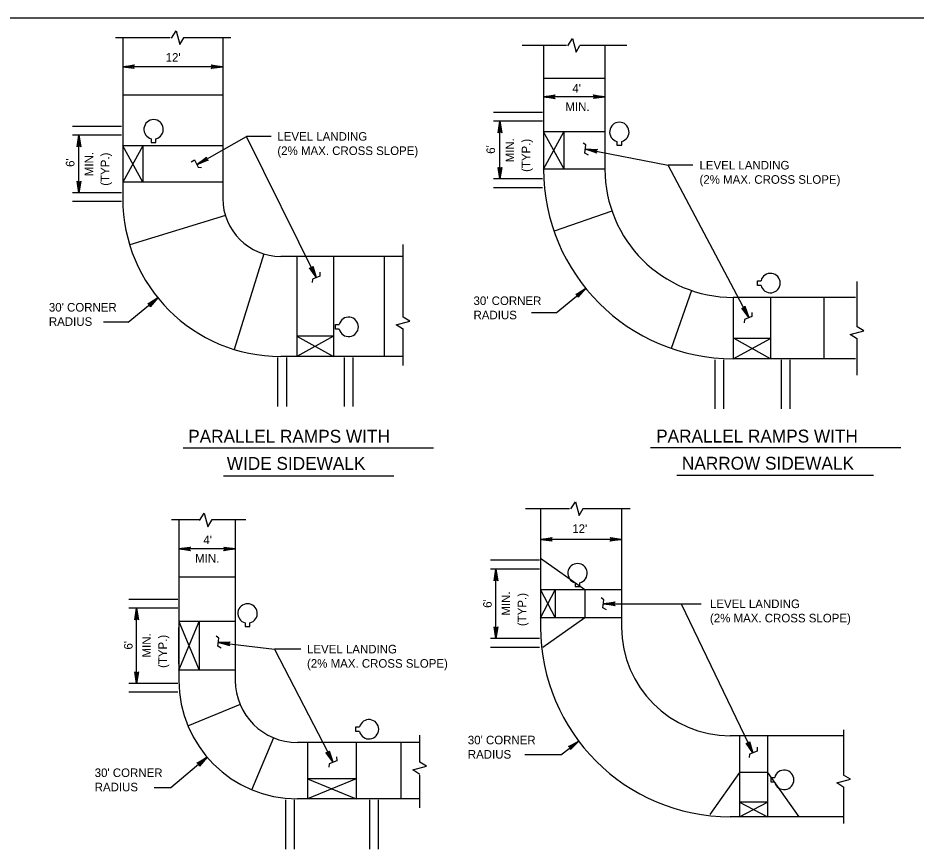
# Model space of a CAD drawing. Extents: x -344 to 940, y 22 to 1233.
# Drawn here: x 84.3 to 398.4, y 310.4 to 601.2 of the extents above; entities that cross this region are included whole.
import ezdxf

# ---------------------------------------------------------------- set-up
doc = ezdxf.new("R2010")
doc.units = 0
doc.layers.add('1', color=7, linetype='Continuous')
doc.layers.add('2', color=7, linetype='Continuous')

msp = doc.modelspace()

# ---------------------------------------------------------------- linework, layer by layer
at = {"layer": '1'}
msp.add_line((75.86, 601.17), (861.86, 601.17), dxfattribs=at)
at = {"layer": '2'}
for p, q in [((137.56, 594.17), (118.38, 594.17)), ((120.93, 594.17), (120.93, 538.02)), ((158.71, 594.17), (142.18, 594.17)), ((155.93, 594.17), (155.93, 538.02)), ((276.13, 591.48), (260.66, 591.48)), ((268.14, 591.48), (268.14, 548.28)), ((297.29, 591.48), (280.76, 591.48)), ((289.58, 591.48), (289.58, 548.28)), ((155.93, 584.11), (120.93, 584.11)), ((289.58, 579.99), (268.14, 579.99)), ((155.93, 574.19), (120.93, 574.19)), ((289.58, 573.58), (268.14, 573.58)), ((267.77, 568.08), (250.6, 568.08)), ((120.56, 563.24), (103.39, 563.24)), ((267.77, 565.01), (250.6, 565.01)), ((252.86, 544.85), (252.86, 565.01)), ((120.56, 560.17), (103.39, 560.17)), ((105.64, 540.01), (105.64, 560.17)), ((146.96, 549.94), (164.24, 559.7)), ((172.85, 559.7), (164.24, 559.7)), ((188.6, 510.44), (164.24, 559.7)), ((289.58, 561.32), (268.14, 561.32)), ((275.22, 548.54), (268.14, 561.32)), ((268.14, 548.28), (275.22, 561.32)), ((275.22, 561.32), (275.22, 548.54)), ((155.93, 556.48), (120.93, 556.48)), ((128.01, 543.7), (120.93, 556.48)), ((128.01, 556.48), (120.93, 543.7)), ((128.01, 556.48), (128.01, 543.7)), ((130.91, 558.91), (130.91, 557.61)), ((130.91, 557.61), (132.56, 557.61)), ((132.56, 557.61), (132.56, 558.91)), ((293.79, 558), (293.79, 556.7)), ((293.79, 556.7), (295.45, 556.7)), ((295.45, 556.7), (295.45, 558)), ((282.85, 555.28), (311.73, 549.64)), ((289.58, 548.28), (268.14, 548.28)), ((320.33, 549.64), (311.73, 549.64)), ((339.89, 496.41), (311.73, 549.64)), ((155.93, 543.7), (120.93, 543.7)), ((267.77, 544.85), (250.6, 544.85)), ((267.77, 541.78), (250.6, 541.78)), ((120.56, 540.01), (103.39, 540.01)), ((120.56, 536.94), (103.39, 536.94)), ((156.83, 532.06), (123.37, 521.78)), ((292.05, 533.62), (271.78, 526.61)), ((219, 496.52), (219, 521.92)), ((170.24, 518.65), (159.96, 485.19)), ((219, 517.75), (176.2, 517.75)), ((181.88, 517.75), (181.88, 482.75)), ((194.66, 517.75), (194.66, 482.75)), ((212.37, 517.75), (212.37, 482.75)), ((342.89, 507.6), (342.89, 509.26)), ((342.89, 509.26), (344.19, 509.26)), ((377.8, 493.14), (377.8, 508.95)), ((272.5, 498.03), (282.95, 506.5)), ((319.81, 505.86), (312.8, 485.59)), ((344.19, 507.6), (342.89, 507.6)), ((122.82, 494.73), (133.27, 503.21)), ((377.26, 503.39), (334.47, 503.39)), ((334.47, 503.39), (334.47, 481.95)), ((347.51, 503.39), (347.51, 481.95)), ((366.18, 503.39), (366.18, 481.95)), ((272.5, 498.03), (263.9, 498.03)), ((122.82, 494.73), (114.22, 494.73)), ((195.35, 492.29), (195.35, 493.94)), ((195.35, 493.94), (196.65, 493.94)), ((196.65, 492.29), (195.35, 492.29)), ((219, 479.61), (219, 492.28)), ((194.66, 489.83), (181.88, 489.83)), ((181.88, 489.83), (194.66, 482.75)), ((194.66, 489.83), (181.88, 482.75)), ((334.47, 481.95), (347.51, 489.03)), ((347.51, 489.03), (334.73, 489.03)), ((347.51, 481.95), (334.73, 489.03)), ((377.8, 476.22), (377.8, 488.89)), ((175.12, 482.38), (175.12, 465.21)), ((219, 482.75), (176.2, 482.75)), ((178.19, 482.38), (178.19, 465.21)), ((198.35, 482.38), (198.35, 465.21)), ((201.42, 482.38), (201.42, 465.21)), ((327.97, 481.58), (327.97, 464.41)), ((331.04, 481.58), (331.04, 464.41)), ((377.26, 481.95), (334.47, 481.95)), ((351.2, 481.58), (351.2, 464.41)), ((354.27, 481.58), (354.27, 464.41)), ((142.08, 450.77), (229.65, 450.77)), ((393.13, 450.77), (305.56, 450.77)), ((156.19, 440.95), (215.73, 440.95)), ((383.51, 441.16), (314.76, 441.16)), ((277.23, 429.45), (261.76, 429.45)), ((267.1, 429.45), (267.1, 388.07)), ((298.38, 429.45), (281.86, 429.45)), ((295.43, 429.45), (295.43, 388.07)), ((147.98, 425.58), (138.03, 425.58)), ((140.57, 425.58), (140.57, 369.43)), ((163.99, 425.58), (152, 425.58)), ((160.29, 425.58), (160.29, 369.43)), ((295.43, 418.78), (267.1, 418.78)), ((160.29, 415.43), (140.57, 415.43)), ((282.55, 401.12), (267.1, 412.06)), ((266.74, 411.45), (249.57, 411.45)), ((266.74, 408.38), (249.57, 408.38)), ((251.45, 384.07), (251.45, 408.38)), ((160.29, 405.6), (140.57, 405.6)), ((279.18, 403.61), (279.18, 402.31)), ((279.18, 402.31), (280.83, 402.31)), ((280.83, 402.31), (280.83, 403.61)), ((295.43, 401.12), (267.1, 401.12)), ((267.1, 401.12), (272.17, 391.33)), ((267.1, 391.33), (272.17, 401.12)), ((272.17, 401.12), (272.17, 391.33)), ((282.55, 401.12), (282.55, 391.33)), ((140.21, 397.72), (123.04, 397.72)), ((289.1, 396.22), (323.27, 396.22)), ((316.27, 396.22), (341.26, 344.13)), ((140.21, 394.65), (123.04, 394.65)), ((125.78, 368.35), (125.78, 394.65)), ((160.29, 390.02), (140.57, 390.02)), ((140.57, 390.02), (147.65, 372.99)), ((140.57, 372.99), (147.65, 390.02)), ((147.65, 390.02), (147.65, 372.99)), ((163.78, 389.54), (163.78, 388.24)), ((165.43, 388.24), (165.43, 389.54)), ((295.43, 391.33), (267.1, 391.33)), ((282.55, 391.33), (267.9, 380.96)), ((140.57, 375.11), (140.57, 387.89)), ((163.78, 388.24), (165.43, 388.24)), ((266.74, 384.07), (249.57, 384.07)), ((154.43, 382.71), (174.05, 380.35)), ((183.17, 380.35), (174.05, 380.35)), ((174.05, 380.35), (194.39, 340.92)), ((266.74, 381), (249.57, 381)), ((160.29, 372.99), (140.57, 372.99)), ((140.21, 368.35), (123.04, 368.35)), ((140.21, 365.28), (123.04, 365.28)), ((161.98, 361.05), (143.61, 353.37)), ((202.47, 351.52), (202.47, 353.17)), ((202.47, 353.17), (203.77, 353.17)), ((373.1, 336.29), (373.1, 352.1)), ((173.64, 349.38), (165.97, 331.01)), ((203.77, 351.52), (202.47, 351.52)), ((224.83, 340.84), (224.83, 350.3)), ((373.1, 350.08), (333.43, 350.08)), ((336.68, 350.08), (336.68, 321.75)), ((346.47, 350.08), (346.47, 321.75)), ((224.83, 347.7), (182.03, 347.7)), ((185.58, 347.7), (185.58, 327.98)), ((202.62, 347.7), (202.62, 327.98)), ((218.2, 347.7), (218.2, 327.98)), ((274.12, 343.44), (280.43, 348.19)), ((150.42, 342.61), (137.74, 331.85)), ((274.12, 343.44), (261.52, 343.44)), ((224.83, 324.83), (224.83, 336.3)), ((336.68, 337.19), (326.31, 322.55)), ((346.47, 337.19), (336.68, 337.19)), ((346.47, 337.19), (357.41, 321.75)), ((202.62, 335.05), (185.58, 335.05)), ((185.58, 335.05), (202.62, 327.98)), ((202.62, 335.05), (185.58, 327.98)), ((347.67, 333.82), (347.67, 335.48)), ((347.67, 335.48), (348.97, 335.48)), ((348.97, 333.82), (347.67, 333.82)), ((137.74, 331.85), (131.91, 331.85)), ((373.1, 319.37), (373.1, 332.05)), ((177.88, 327.61), (177.88, 310.44)), ((180.95, 327.61), (180.95, 310.44)), ((224.83, 327.98), (182.03, 327.98)), ((207.25, 327.61), (207.25, 310.44)), ((210.32, 327.61), (210.32, 310.44)), ((346.47, 326.82), (336.68, 326.82)), ((336.68, 326.82), (346.47, 321.75)), ((336.68, 321.75), (346.47, 326.82)), ((373.1, 321.75), (333.43, 321.75))]:
    msp.add_line(p, q, dxfattribs=at)
for points in [[(137.98, 594.14), (139.67, 596.62), (140.93, 591.88), (142.29, 594.25)], [(276.56, 591.46), (278.24, 593.94), (279.51, 589.2), (280.86, 591.57)], [(124.79, 583.62), (124.65, 583.9), (120.93, 584.11), (124.79, 583.62), (124.99, 583.45), (120.93, 584.11), (124.64, 584.29), (124.78, 584.57), (120.93, 584.11), (124.99, 584.75), (124.78, 584.57)], [(152.07, 584.59), (152.22, 584.31), (155.93, 584.11), (152.07, 584.59), (151.87, 584.76), (155.93, 584.11), (152.22, 583.92), (152.08, 583.65), (155.93, 584.11), (151.87, 583.46), (152.08, 583.65)], [(272, 573.1), (271.86, 573.38), (268.14, 573.58), (272, 573.1), (272.2, 572.93), (268.14, 573.58), (271.85, 573.77), (271.99, 574.04), (268.14, 573.58), (272.2, 574.23), (271.99, 574.04)], [(285.72, 574.07), (285.87, 573.79), (289.58, 573.58), (285.72, 574.07), (285.53, 574.24), (289.58, 573.58), (285.87, 573.4), (285.74, 573.12), (289.58, 573.58), (285.53, 572.94), (285.74, 573.12)], [(252.37, 561.15), (252.65, 561.29), (252.86, 565.01), (252.37, 561.15), (252.2, 560.95), (252.86, 565.01), (253.04, 561.3), (253.32, 561.16), (252.86, 565.01), (253.5, 560.95), (253.32, 561.16)], [(105.16, 556.31), (105.44, 556.46), (105.64, 560.17), (105.16, 556.31), (104.99, 556.11), (105.64, 560.17), (105.83, 556.46), (106.1, 556.32), (105.64, 560.17), (106.29, 556.11), (106.1, 556.32)], [(283.82, 553.2), (282.6, 553.89), (282.96, 556.73), (282.02, 557.37)], [(286.55, 554.07), (286.46, 554.37), (282.85, 555.28), (286.55, 554.07), (286.71, 553.86), (282.85, 555.28), (286.53, 554.75), (286.72, 555), (282.85, 555.28), (286.96, 555.14), (286.72, 555)], [(144.82, 550.89), (146.05, 551.51), (147.29, 548.92), (148.43, 548.89)], [(150.56, 551.42), (150.3, 551.59), (146.96, 549.94), (150.56, 551.42), (150.82, 551.37), (146.96, 549.94), (150.1, 551.93), (150.09, 552.24), (146.96, 549.94), (150.18, 552.5), (150.09, 552.24)], [(253.34, 548.71), (253.06, 548.57), (252.86, 544.85), (253.34, 548.71), (253.51, 548.91), (252.86, 544.85), (252.67, 548.56), (252.4, 548.7), (252.86, 544.85), (252.21, 548.91), (252.4, 548.7)], [(106.13, 543.87), (105.85, 543.73), (105.64, 540.01), (106.13, 543.87), (106.3, 544.07), (105.64, 540.01), (105.46, 543.73), (105.18, 543.86), (105.64, 540.01), (105, 544.07), (105.18, 543.86)], [(187.32, 514.12), (187.13, 513.86), (188.6, 510.44), (187.32, 514.12), (187.39, 514.37), (188.6, 510.44), (186.79, 513.69), (186.48, 513.69), (188.6, 510.44), (186.22, 513.79), (186.48, 513.69)], [(189.87, 512.22), (189.92, 510.87), (187.27, 509.77), (187.18, 508.63)], [(279.65, 504.44), (279.94, 504.32), (282.95, 506.5), (279.65, 504.44), (279.39, 504.45), (282.95, 506.5), (280.18, 504.02), (280.25, 503.72), (282.95, 506.5), (280.21, 503.44), (280.25, 503.72)], [(129.97, 501.15), (130.26, 501.03), (133.27, 503.21), (129.97, 501.15), (129.71, 501.16), (133.27, 503.21), (130.5, 500.73), (130.57, 500.43), (133.27, 503.21), (130.53, 500.15), (130.57, 500.43)], [(338.51, 500.05), (338.33, 499.79), (339.89, 496.41), (338.51, 500.05), (338.57, 500.3), (339.89, 496.41), (337.99, 499.61), (337.68, 499.6), (339.89, 496.41), (337.42, 499.7), (337.68, 499.6)], [(219.08, 492.15), (216.6, 493.84), (221.34, 495.1), (218.97, 496.46)], [(340.94, 498.11), (340.98, 496.76), (338.34, 495.66), (338.25, 494.53)], [(377.88, 488.77), (375.4, 490.45), (380.14, 491.72), (377.77, 493.08)], [(277.65, 429.42), (279.34, 431.9), (280.6, 427.17), (281.96, 429.53)], [(147.77, 425.42), (149.46, 427.9), (150.72, 423.16), (152.08, 425.53)], [(270.96, 418.3), (270.82, 418.58), (267.1, 418.78), (270.96, 418.3), (271.16, 418.13), (267.1, 418.78), (270.82, 418.97), (270.95, 419.24), (267.1, 418.78), (271.16, 419.43), (270.95, 419.24)], [(291.57, 419.27), (291.72, 418.99), (295.43, 418.78), (291.57, 419.27), (291.37, 419.44), (295.43, 418.78), (291.72, 418.6), (291.58, 418.32), (295.43, 418.78), (291.37, 418.14), (291.58, 418.32)], [(144.43, 414.94), (144.29, 415.22), (140.57, 415.43), (144.43, 414.94), (144.63, 414.77), (140.57, 415.43), (144.29, 415.61), (144.42, 415.89), (140.57, 415.43), (144.63, 416.07), (144.42, 415.89)], [(156.43, 415.91), (156.58, 415.63), (160.29, 415.43), (156.43, 415.91), (156.24, 416.08), (160.29, 415.43), (156.58, 415.24), (156.45, 414.97), (160.29, 415.43), (156.24, 414.78), (156.45, 414.97)], [(250.96, 404.52), (251.24, 404.66), (251.45, 408.38), (250.96, 404.52), (250.79, 404.32), (251.45, 408.38), (251.63, 404.67), (251.91, 404.53), (251.45, 408.38), (252.09, 404.32), (251.91, 404.53)], [(290.09, 394.13), (288.87, 394.82), (289.23, 397.66), (288.29, 398.3)], [(292.96, 395.74), (292.82, 396.02), (289.1, 396.22), (292.96, 395.74), (293.16, 395.57), (289.1, 396.22), (292.82, 396.41), (292.95, 396.68), (289.1, 396.22), (293.16, 396.87), (292.95, 396.68)], [(125.29, 390.79), (125.57, 390.94), (125.78, 394.65), (125.29, 390.79), (125.12, 390.59), (125.78, 394.65), (125.96, 390.94), (126.24, 390.8), (125.78, 394.65), (126.42, 390.59), (126.24, 390.8)], [(251.93, 387.93), (251.65, 387.79), (251.45, 384.07), (251.93, 387.93), (252.1, 388.13), (251.45, 384.07), (251.26, 387.78), (250.99, 387.92), (251.45, 384.07), (250.8, 388.13), (250.99, 387.92)], [(155.4, 380.7), (154.18, 381.4), (154.54, 384.24), (153.6, 384.88)], [(158.21, 381.77), (158.1, 382.06), (154.43, 382.71), (158.21, 381.77), (158.38, 381.58), (154.43, 382.71), (158.14, 382.45), (158.31, 382.71), (154.43, 382.71), (158.54, 382.87), (158.31, 382.71)], [(126.26, 372.21), (125.98, 372.07), (125.78, 368.35), (126.26, 372.21), (126.43, 372.41), (125.78, 368.35), (125.59, 372.07), (125.32, 372.2), (125.78, 368.35), (125.13, 372.41), (125.32, 372.2)], [(277.06, 346.26), (277.34, 346.12), (280.43, 348.19), (277.06, 346.26), (276.8, 346.27), (280.43, 348.19), (277.58, 345.81), (277.64, 345.51), (280.43, 348.19), (277.58, 345.24), (277.64, 345.51)], [(340.03, 347.82), (339.84, 347.56), (341.26, 344.13), (340.03, 347.82), (340.1, 348.07), (341.26, 344.13), (339.49, 347.39), (339.18, 347.4), (341.26, 344.13), (338.93, 347.51), (339.18, 347.4)], [(342.77, 346.05), (342.81, 344.7), (340.17, 343.6), (340.08, 342.47)], [(147.16, 340.48), (147.45, 340.36), (150.42, 342.61), (147.16, 340.48), (146.9, 340.48), (150.42, 342.61), (147.71, 340.07), (147.78, 339.77), (150.42, 342.61), (147.74, 339.49), (147.78, 339.77)], [(193.05, 344.58), (192.87, 344.32), (194.39, 340.92), (193.05, 344.58), (193.11, 344.83), (194.39, 340.92), (192.53, 344.14), (192.22, 344.13), (194.39, 340.92), (191.96, 344.23), (192.22, 344.13)], [(195.74, 342.7), (195.79, 341.35), (193.14, 340.25), (193.05, 339.11)], [(224.9, 336.47), (222.43, 338.16), (227.16, 339.42), (224.79, 340.78)], [(373.18, 331.92), (370.7, 333.61), (375.44, 334.87), (373.07, 336.23)]]:
    msp.add_lwpolyline(points, dxfattribs=at)
for centre, radius, start, end in [((131.74, 562.21), 3.4, 284.1014, 255.8986), ((294.62, 561.29), 3.4, 284.1014, 255.8986), ((334.47, 548.28), 66.33, 180, 270), ((334.47, 548.28), 44.88, 180, 270), ((176.2, 538.02), 55.27, 180, 270), ((176.2, 538.02), 20.27, 180, 270), ((347.48, 508.43), 3.4, 194.1014, 165.8986), ((199.95, 493.11), 3.4, 194.1014, 165.8986), ((280.01, 406.91), 3.4, 284.1014, 255.8986), ((164.6, 392.84), 3.4, 284.1014, 255.8986), ((333.43, 388.07), 66.33, 180, 270), ((333.43, 388.07), 38, 180, 270), ((182.03, 369.43), 41.45, 180, 270), ((182.03, 369.43), 21.73, 180, 270), ((207.07, 352.34), 3.4, 194.1014, 165.8986), ((352.26, 334.65), 3.4, 194.1014, 165.8986)]:
    msp.add_arc(centre, radius, start, end, dxfattribs=at)

# ---------------------------------------------------------------- texts
for s, height, p in [("12'", 3, (135.94, 585.86)), ("4'", 3, (278.2, 575.07)), ('MIN.', 3, (275.76, 568.64)), ('LEVEL LANDING', 3, (175.02, 558.23)), ('(2% MAX. CROSS SLOPE)', 3, (175.02, 553.23)), ('LEVEL LANDING', 3, (322.66, 548.16)), ('(2% MAX. CROSS SLOPE)', 3, (322.66, 543.16)), ("30' CORNER", 3, (243.63, 500.75)), ("30' CORNER", 3, (95.11, 498.46)), ('RADIUS', 3, (95.11, 493.46)), ('RADIUS', 3, (243.63, 495.75)), ('PARALLEL RAMPS WITH', 4.5, (143.83, 452.59)), ('PARALLEL RAMPS WITH', 4.5, (307.5, 452.65)), ('WIDE SIDEWALK', 4.5, (157.33, 443.09)), ('NARROW SIDEWALK', 4.5, (316.5, 443.15)), ("12'", 3, (278.17, 421.02)), ("4'", 3, (149.14, 417.1)), ('MIN.', 3, (146.26, 410.64)), ('LEVEL LANDING', 3, (326.32, 394.73)), ('(2% MAX. CROSS SLOPE)', 3, (326.32, 389.73)), ('LEVEL LANDING', 3, (185.39, 378.87)), ('(2% MAX. CROSS SLOPE)', 3, (185.39, 373.87)), ("30' CORNER", 3, (241.63, 347.07)), ('RADIUS', 3, (241.63, 342.07)), ("30' CORNER", 3, (111.13, 335.63)), ('RADIUS', 3, (111.13, 330.63))]:
    msp.add_text(s, height=height, dxfattribs=at).set_placement(p)
for s, p in [("6'", (251.15, 553.65)), ('MIN.', (257.82, 550.66)), ('(TYP.)', (263.47, 547.31)), ('MIN.', (110.61, 545.83)), ('(TYP.)', (116.25, 542.47)), ("6'", (104.05, 549.07)), ('MIN.', (256.42, 392.09)), ('(TYP.)', (262.06, 388.43)), ("6'", (250, 394.82)), ('MIN.', (130.74, 377.45)), ('(TYP.)', (136.39, 373.79)), ("6'", (124.37, 380.23))]:
    msp.add_text(s, height=3, rotation=90, dxfattribs=at).set_placement(p)

doc.saveas('drawing.dxf')
